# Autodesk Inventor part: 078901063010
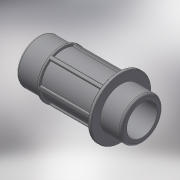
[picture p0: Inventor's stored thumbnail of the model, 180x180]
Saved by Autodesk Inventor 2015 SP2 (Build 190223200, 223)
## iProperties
Created: 2018-02
Part Number: 078901063010
Material: Generic
Description: PLASSON THREADED MALE ADAPTOR 63-1"
Document SubType Name: Modeling
Designer: KIM
Density: 1 g/cm^3
Appearance: Default
Author: KIM
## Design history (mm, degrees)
derived "078901.ipt"
feature "Solid1::078901.ipt"
tag "TaggingFeature1"
body "Solid1"
other parameters: "d4" = 1.66245, "d14" = 2.65992, "d15" = 1.32996, "d17" = 0, "d20" = 360 deg, "d41" = 33.249, "d45" = 36.5739, "d46" = 23.2743, "d47" = 2, "d77" = 108, "d78" = 63, "d85" = 0.33249, "d91" = 21.6, "d103" = 24.84, "d104" = 83, "d105" = 0.33249, "R_" = 33.249, "E_" = 83, "l_" = 108, "d_" = 63
